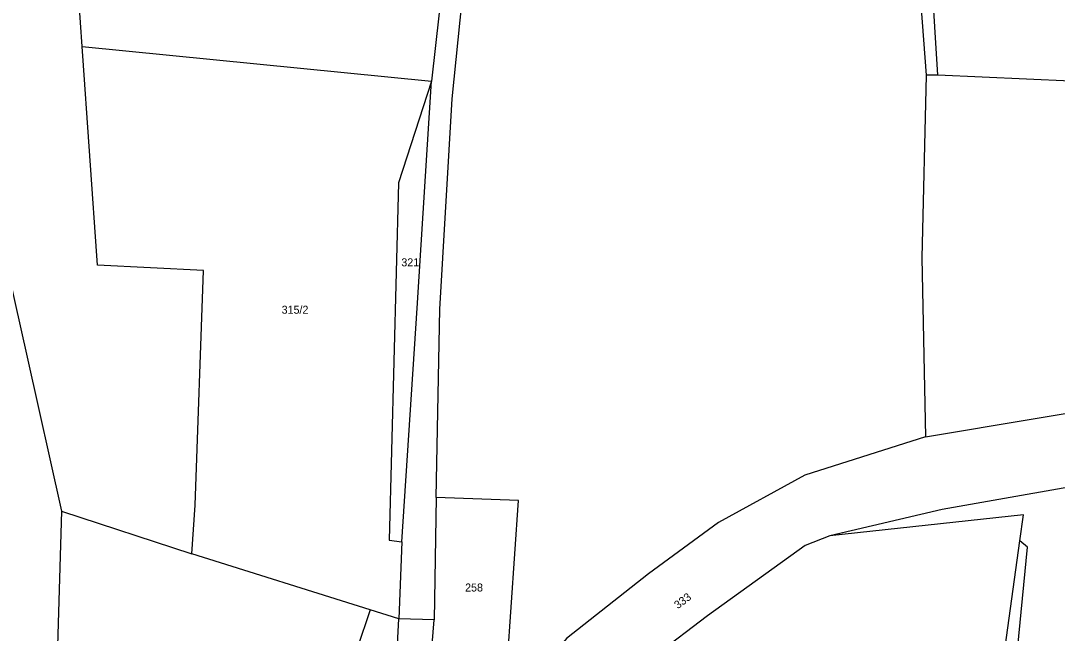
# Model space of a CAD drawing. Extents: x -880531 to -877616, y -1023932 to -1021350.
# Drawn here: x -878781.4 to -878561.2, y -1022327.2 to -1022197 of the extents above; entities that cross this region are included whole.
import ezdxf

# ---------------------------------------------------------------- set-up
doc = ezdxf.new("R2010")
doc.units = 0
doc.layers.add('Hranice parcel', color=7, linetype='Continuous')
doc.layers.add('Parcelní čísla', color=7, linetype='Continuous')

msp = doc.modelspace()

# ---------------------------------------------------------------- linework, layer by layer
at = {"layer": 'Hranice parcel'}
for p, q in [((-878768.4, -1022202.48), (-878694.18, -1022209.89)), ((-878586.62, -1022208.6), (-878589.06, -1022208.62)), ((-878693.21, -1022298.36), (-878693.64, -1022324.29)), ((-878772.79, -1022301.21), (-878745.08, -1022310.27)), ((-878700.45, -1022307.74), (-878701.15, -1022324.12)), ((-878579.47, -1022381.89), (-878569.16, -1022307.52)), ((-878707.2, -1022322.19), (-878745.08, -1022310.27)), ((-878701.15, -1022324.12), (-878707.2, -1022322.19)), ((-878702.35, -1022346.99), (-878701.15, -1022324.12)), ((-878693.64, -1022324.29), (-878701.15, -1022324.12)), ((-878694.27, -1022332.2), (-878693.64, -1022324.29))]:
    msp.add_line(p, q, dxfattribs=at)
for points in [[(-878693.21, -1022298.36), (-878692.4, -1022258.3), (-878689.78, -1022213.59), (-878684.22, -1022158.54), (-878682.26, -1022103.14), (-878673.47, -1022036.72), (-878669.09, -1021992.24), (-878665.96, -1021938.56), (-878659.56, -1021864.21), (-878651.12, -1021830.64), (-878647.4, -1021802.19), (-878644.62, -1021778.59), (-878640.81, -1021757.55), (-878636.77, -1021734.3), (-878635.51, -1021701.34), (-878633.33, -1021667.69), (-878631.59, -1021625.86), (-878630.9, -1021607.55), (-878630.94, -1021582.96), (-878627.58, -1021573.01)], [(-878586.62, -1022208.6), (-878589.91, -1022154.89), (-878571.07, -1022003.66), (-878565.03, -1021980.86), (-878569.45, -1021980.25), (-878574.67, -1022003.38), (-878593.2, -1022154.07), (-878589.06, -1022208.62)], [(-878796.62, -1022014.79), (-878799.81, -1022095.23), (-878802.22, -1022134.81), (-878802.77, -1022161.7), (-878801.33, -1022180.04), (-878788.12, -1022233), (-878780.08, -1022268.54), (-878772.79, -1022301.21)], [(-878768.4, -1022202.48), (-878769.12, -1022192.22), (-878768.28, -1022125.33), (-878761.32, -1022093.01), (-878746.55, -1022089.12), (-878733.6, -1022035.04)], [(-878676.69, -1022035.16), (-878688.26, -1022101.67), (-878688.42, -1022158.68), (-878694.18, -1022209.89)], [(-878745.08, -1022310.27), (-878744.37, -1022299.96), (-878742.62, -1022250.12), (-878765.12, -1022248.99), (-878768.4, -1022202.48)], [(-878589.06, -1022208.62), (-878590, -1022247.37), (-878589.21, -1022285.43)], [(-878461.63, -1022254.79), (-878477.42, -1022247.38), (-878501.8, -1022232.02), (-878527.45, -1022220.17), (-878558.36, -1022209.87), (-878586.62, -1022208.6)], [(-878694.18, -1022209.89), (-878701.22, -1022231.48), (-878703.15, -1022307.41), (-878700.45, -1022307.74)], [(-878700.45, -1022307.74), (-878697.19, -1022258.12), (-878694.18, -1022209.89)], [(-878589.21, -1022285.43), (-878519.72, -1022273.83), (-878469.66, -1022258.46), (-878461.63, -1022254.79)], [(-878466.42, -1022273.02), (-878507.75, -1022287.12), (-878585.67, -1022300.91), (-878609.56, -1022306.45)], [(-878589.21, -1022285.43), (-878614.84, -1022293.57), (-878633.22, -1022303.64), (-878648.06, -1022314.55), (-878665.5, -1022328.26), (-878678.8, -1022344.27)], [(-878678.8, -1022344.27), (-878675.7, -1022298.99), (-878693.21, -1022298.36)], [(-878772.79, -1022301.21), (-878773.84, -1022336.98), (-878774.14, -1022349.64)], [(-878569.16, -1022307.52), (-878568.4, -1022302), (-878609.56, -1022306.45)], [(-878609.56, -1022306.45), (-878614.79, -1022308.53), (-878635.51, -1022323.46), (-878657.51, -1022340.21), (-878671.6, -1022358.7)], [(-878575.47, -1022390.32), (-878567.58, -1022308.88), (-878569.16, -1022307.52)], [(-878707.2, -1022322.19), (-878709.98, -1022330.39), (-878712.42, -1022335.85)]]:
    msp.add_lwpolyline(points, dxfattribs=at)

# ---------------------------------------------------------------- texts
at = {"layer": 'Parcelní čísla'}
for s, p in [('321', (-878700.59, -1022249.21)), ('315/2', (-878726.02, -1022259.28)), ('258', (-878687.04, -1022318.3))]:
    msp.add_text(s, height=1.7, dxfattribs=at).set_placement(p)
msp.add_text('333', height=1.7, rotation=37, dxfattribs=at).set_placement((-878641.838, -1022322.088))

doc.saveas('drawing.dxf')
